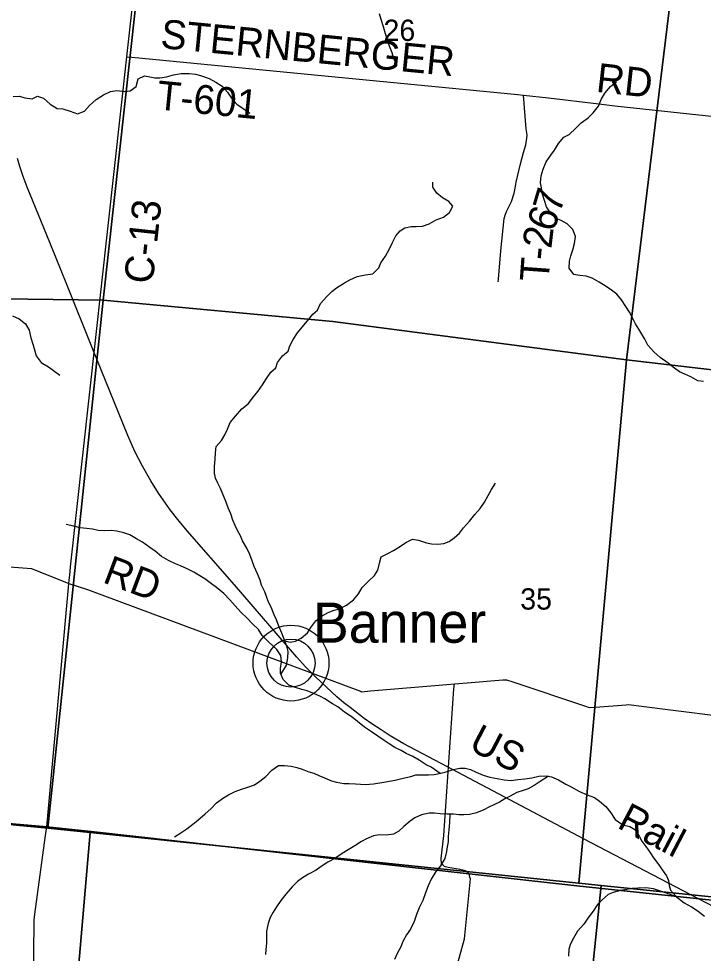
# Model space of a CAD drawing. Extents: x 1715311 to 2083412, y 146837 to 553079.
# Drawn here: x 1938656 to 1945751, y 339371 to 349055 of the extents above; entities that cross this region are included whole.
import ezdxf

# ---------------------------------------------------------------- set-up
doc = ezdxf.new("R2010")
doc.units = 0
for name, color, linetype in [('GM_X_County_Road', 7, 'Continuous'), ('GM_X_County_Road_Text', 7, 'Continuous'), ('GM_X_Major_River', 7, 'Continuous'), ('GM_X_Minor_River', 7, 'Continuous'), ('GM_X_Rail_Line', 7, 'Continuous'), ('GM_X_Rail_Line_Text', 7, 'Continuous'), ('GM_X_Section', 7, 'Continuous'), ('GM_X_Section_Text', 7, 'Continuous'), ('GM_X_Township', 7, 'Continuous'), ('GM_X_Township_Road', 7, 'Continuous'), ('GM_X_Township_Road_Text', 7, 'Continuous'), ('GM_X_Unincorporated', 7, 'Continuous'), ('GM_X_Unincorporated_Location', 7, 'Continuous'), ('GM_X_Unincorporated_Text', 7, 'Continuous')]:
    doc.layers.add(name, color=color, linetype=linetype)

msp = doc.modelspace()

# ---------------------------------------------------------------- linework, layer by layer
at = {"layer": 'GM_X_County_Road'}
for points in [[(1938935.2, 340590.1), (1938947.9, 340681.2), (1939172.8, 343162.1), (1939176.8, 343201), (1939183.7, 343268), (1939185, 343285.8), (1939194.7, 343373.7), (1939777.7, 348661.1), (1939894.4, 349718.8), (1939895.9, 349732.8), (1939820.2, 349785.7), (1939515.1, 349999.1), (1939497.4, 350011.3), (1939503.1, 350096.1), (1939538.8, 350627.1), (1939541.5, 350666.8), (1939516.4, 350728.3), (1939415.8, 350974.7), (1939407.4, 350995.5), (1939345.3, 351051.9), (1939188, 351195.2), (1939148.3, 351231.3)], [(1931545.1, 344105.6), (1934080.4, 345204.9), (1934175.4, 345216.4), (1934810.6, 345293.7), (1935110.9, 344920.9), (1935323.1, 343756.7), (1935469.2, 343608.4), (1938788.6, 343357.9), (1939176.8, 343201)], [(1939176.8, 343201), (1939370, 343141), (1942197.7, 342086.2), (1942210, 342081.6), (1942302.3, 342089.4), (1943093.7, 342157.2), (1943171, 342163.7), (1943304.8, 342174.2), (1943674.3, 342203.1), (1943709.5, 342205.8), (1943776.4, 342183.3), (1944529.4, 341930.5), (1944568.4, 341917.3), (1944632.8, 341922), (1944949.7, 341945.2), (1944978.8, 341947.3), (1945054.9, 341937.7), (1946315.5, 341777.9)], [(1943060.7, 340276.9), (1943038.5, 340300.6), (1943032.8, 340353.3), (1943061, 340592.3), (1943165.7, 342109.8), (1943171, 342163.7)], [(1938808.1, 339138.3), (1938815.9, 339670.2), (1938816.6, 339717.3), (1938822.6, 339776.1), (1938935.2, 340590.1)], [(1943332.5, 340160.3), (1943322.9, 340193.4), (1943291.1, 340224.1), (1943209.7, 340244.2), (1943108.1, 340259.2), (1943066.7, 340270.5), (1943060.7, 340276.9)], [(1943194.4, 339218.7), (1943275.6, 339519.6), (1943337.7, 340142.5), (1943332.5, 340160.3)]]:
    msp.add_lwpolyline(points, dxfattribs=at)
at = {"layer": 'GM_X_Major_River'}
msp.add_lwpolyline([(1942390.9, 349109.3), (1942408.3, 349051.1), (1942433.6, 348972.8), (1942454.9, 348902.6), (1942476.3, 348834.4), (1942495.7, 348774.1), (1942523, 348705.8), (1942540.4, 348645.6), (1942571.8, 348579.3)], dxfattribs=at)
at = {"layer": 'GM_X_Minor_River'}
for points in [[(1938598.9, 348247.8), (1938664.8, 348251.5), (1938720.6, 348233.2), (1938796.4, 348224.8), (1938852.4, 348252.6), (1938914.1, 348230.3), (1938983.7, 348168), (1939055.3, 348125.6), (1939115.2, 348121.3), (1939190.9, 348095), (1939264.6, 348068.6), (1939336.6, 348096.3), (1939388.7, 348154.1), (1939458.8, 348215.8), (1939536.9, 348265.5), (1939606.9, 348301.2), (1939672.8, 348309), (1939756.5, 348300.6), (1939810.5, 348306.3), (1939872.5, 348352.1), (1939894.8, 348430), (1939958.8, 348461.8), (1940014.6, 348453.5), (1940066.5, 348441.3), (1940120.3, 348441), (1940186.3, 348452.7), (1940262.2, 348474.4), (1940340.1, 348486.1), (1940423.9, 348485.7), (1940489.7, 348479.4), (1940541.5, 348467.1), (1940629.2, 348434.7), (1940698.9, 348398.4), (1940764.5, 348356.1), (1940820.1, 348291.8), (1940861.8, 348229.5), (1940915.4, 348167.3), (1940983.1, 348124.9), (1941050.7, 348076.6)], [(1945752, 345296), (1945694.1, 345302.2), (1945622.5, 345344.6), (1945560.7, 345370.9), (1945505, 345395.1), (1945451.3, 345433.4), (1945385.6, 345485.7), (1945304.1, 345544.1), (1945238.5, 345602.4), (1945176.9, 345670.7), (1945143.3, 345732.9), (1945113.6, 345785.1), (1945081.9, 345839.2), (1945048.2, 345893.4), (1945014.6, 345963.6), (1944984.8, 346013.8), (1944949.2, 346072), (1944903.6, 346140.2), (1944854, 346200.5), (1944800.3, 346240.7), (1944742.6, 346279), (1944672.9, 346325.3), (1944597.3, 346367.7), (1944535.5, 346388), (1944469.7, 346392.3), (1944407.8, 346402.6), (1944360.2, 346470.8), (1944362.6, 346542.8), (1944376.8, 346598.8), (1944397, 346660.8), (1944417.2, 346726.7), (1944425.5, 346796.7), (1944397.9, 346870.9), (1944338.3, 346929.2), (1944278.6, 346963.5), (1944224.8, 346983.7), (1944159.2, 347052), (1944125.6, 347106.2), (1944099.9, 347180.4), (1944080.3, 347248.5), (1944072.5, 347302.6), (1944064.8, 347352.6), (1944069.1, 347424.7), (1944091.3, 347496.6), (1944123.6, 347572.5), (1944171.8, 347640.3), (1944207.9, 347692.2), (1944250.1, 347762.1), (1944306.3, 347825.9), (1944360.3, 347855.6), (1944428.4, 347919.4), (1944486.5, 347975.2), (1944558.6, 348026.9), (1944610.7, 348080.7), (1944662.9, 348148.5), (1944693.1, 348216.4), (1944731.3, 348284.3), (1944787.5, 348352.1), (1944849.6, 348403.8)], [(1941373.9, 342259.9), (1941430.9, 342355.8), (1941445.2, 342433.8), (1941447.5, 342497.8), (1941433.7, 342551.9), (1941382.4, 342688.2), (1941352.8, 342760.3), (1941327.2, 342826.5), (1941303.4, 342878.6), (1941271.9, 342956.8), (1941246.1, 343008.9), (1941226.4, 343059), (1941206.7, 343115.2), (1941173.1, 343185.3), (1941157.3, 343235.5), (1941129.7, 343303.6), (1941098.1, 343377.8), (1941076.4, 343435.9), (1941052.7, 343502), (1941019.1, 343568.2), (1940975.5, 343644.5), (1940953.8, 343696.6), (1940924.1, 343752.7), (1940900.4, 343804.9), (1940874.7, 343857), (1940853, 343923.1), (1940827.3, 343987.3), (1940799.7, 344061.4), (1940772.1, 344127.6), (1940746.4, 344185.7), (1940718.7, 344241.9), (1940695, 344294), (1940685.2, 344346.1), (1940685.5, 344416.1), (1940693.9, 344492.1), (1940696.1, 344556.1), (1940702.4, 344622.1), (1940756.5, 344683.9), (1940792.7, 344741.8), (1940818.9, 344801.7), (1940849.2, 344869.6), (1940901.3, 344937.4), (1940969.5, 345011.1), (1941035.6, 345062.9), (1941089.8, 345136.7), (1941135.9, 345190.5), (1941184.1, 345260.3), (1941224.3, 345328.2), (1941268.5, 345392), (1941320.6, 345437.8), (1941338.8, 345491.8), (1941389, 345561.6), (1941449, 345611.3), (1941465.2, 345663.3), (1941499.4, 345729.2), (1941545.7, 345801), (1941593.8, 345856.8), (1941650, 345924.6), (1941704.1, 345992.4), (1941754.2, 346036.2), (1941782.5, 346104.1), (1941850.6, 346177.8), (1941900.7, 346229.6), (1941950.8, 346267.5), (1942030.8, 346319.1), (1942088.8, 346348.9), (1942162.8, 346382.6), (1942250.7, 346402.2), (1942324.6, 346411.8), (1942386.7, 346471.6), (1942408.9, 346523.5), (1942457.1, 346595.4), (1942497.3, 346669.2), (1942529.5, 346735.1), (1942565.7, 346805), (1942607.9, 346856.8), (1942657.9, 346886.6), (1942723.8, 346900.4), (1942775.7, 346900.1), (1942841.6, 346903.8), (1942911.5, 346927.5), (1942981.5, 346969.2), (1943057.5, 346998.9), (1943119.6, 347046.7), (1943153.8, 347110.6), (1943112.1, 347160.8), (1943048.4, 347197.1), (1942988.7, 347247.4), (1942949.1, 347309.6), (1942949.3, 347361.6)], [(1938593, 345976.3), (1938660.7, 345944), (1938726.4, 345893.7), (1938766, 345827.5), (1938783.6, 345749.4), (1938805.2, 345673.2), (1938819, 345623.1), (1938838.7, 345561), (1938890.2, 345492.7), (1938963.9, 345446.4), (1939015.6, 345408.1), (1939083.2, 345359.8)], [(1941412.7, 342607.7), (1941467.8, 342595.8), (1941523.8, 342605.5), (1941583.8, 342637.3), (1941647.9, 342693), (1941684, 342744.9), (1941736.2, 342816.7), (1941800.3, 342866.4), (1941862.3, 342902.1), (1941924.3, 342927.9), (1941980.2, 342941.6), (1942052.2, 342977.3), (1942126.3, 343033), (1942176.4, 343096.8), (1942216.6, 343160.7), (1942276.8, 343224.4), (1942344.9, 343286.1), (1942377.1, 343340), (1942395.3, 343412), (1942413.6, 343479.9), (1942489.6, 343517.6), (1942541.6, 343545.4), (1942603.6, 343583.1), (1942669.6, 343626.8), (1942737.6, 343660.6), (1942799.5, 343652.3), (1942883.1, 343623.9), (1942935, 343613.6), (1943000.8, 343609.4), (1943062.7, 343617.1), (1943118.7, 343638.8), (1943168.7, 343674.6), (1943222.8, 343724.4), (1943267, 343780.2), (1943327.1, 343848), (1943383.3, 343917.8), (1943437.5, 343979.6), (1943481.6, 344045.4), (1943519.9, 344115.3), (1943554.1, 344175.2), (1943596.3, 344243)], [(1943024.6, 341234.9), (1942930.9, 341298.6), (1942877.1, 341324.9), (1942807.5, 341373.2), (1942739.8, 341409.5), (1942672.1, 341441.8), (1942618.4, 341472.1), (1942552.6, 341504.4), (1942496.9, 341540.7), (1942445.2, 341576.9), (1942377.6, 341621.2), (1942313.9, 341665.6), (1942238.3, 341713.9), (1942166.7, 341772.3), (1942113, 341816.5), (1942033.4, 341868.9), (1941961.8, 341923.2), (1941908.1, 341955.5), (1941828.5, 342005.9), (1941776.7, 342034.1), (1941722.9, 342060.4), (1941645.2, 342088.8), (1941591.4, 342105), (1941523.7, 342123.3), (1941455.9, 342147.6), (1941396.3, 342207.9), (1941368.7, 342272.1), (1941368.9, 342322.1), (1941379.1, 342390.1), (1941371.4, 342456.1), (1941331.8, 342520.3), (1941248.3, 342594.8), (1941180.8, 342665.1), (1941141.1, 342727.3), (1941077.5, 342783.6), (1941023.9, 342841.9), (1940958.3, 342906.2), (1940900.7, 342970.5), (1940845.2, 343034.8), (1940783.6, 343099.1), (1940706, 343161.4), (1940654.3, 343197.7), (1940586.7, 343250), (1940532.9, 343282.3), (1940471.2, 343318.6), (1940401.5, 343352.9), (1940333.8, 343385.2), (1940280, 343407.5), (1940208.4, 343441.8), (1940136.7, 343482.1), (1940069.1, 343536.5), (1940015.4, 343576.7), (1939939.8, 343629.1), (1939878.1, 343665.4), (1939806.4, 343705.7), (1939746.6, 343726), (1939674.9, 343746.3), (1939615, 343750.6), (1939545.2, 343748.9), (1939479.3, 343753.2), (1939419.5, 343765.5), (1939361.7, 343771.8), (1939291.9, 343780.1), (1939228.1, 343796.4), (1939148.3, 343812.7)], [(1940271.7, 340576.3), (1940337.8, 340620), (1940397.8, 340661.8), (1940461.9, 340709.5), (1940511.9, 340751.3), (1940588, 340815), (1940648.1, 340868.7), (1940706.3, 340930.5), (1940780.3, 340980.2), (1940830.4, 341012), (1940898.4, 341047.7), (1940966.3, 341071.4), (1941032.3, 341091.1), (1941098.2, 341116.8), (1941154.3, 341154.6), (1941218.3, 341202.3), (1941278.5, 341270), (1941348.5, 341315.8), (1941412.4, 341317.5), (1941478.2, 341311.2), (1941538, 341296.9), (1941593.8, 341278.6), (1941661.5, 341252.3), (1941713.4, 341236.1), (1941765.2, 341213.8), (1941824.9, 341187.5), (1941896.6, 341159.2), (1941950.4, 341143), (1942024.2, 341130.6), (1942082.1, 341130.4), (1942145.9, 341128.1), (1942197.8, 341121.8), (1942251.7, 341121.6), (1942333.5, 341125.2), (1942441.3, 341144.8), (1942497.3, 341154.5), (1942557.2, 341166.2), (1942639.1, 341185.9), (1942719, 341203.5), (1942772.9, 341219.3), (1942902.6, 341218.7), (1942960.5, 341224.5), (1943032.4, 341236.1), (1943084.4, 341251.9), (1943158.3, 341273.6), (1943228.2, 341289.3), (1943284.1, 341289), (1943337.9, 341274.8), (1943395.6, 341246.5), (1943469.3, 341218.2), (1943539.1, 341195.8), (1943614.9, 341181.5), (1943688.6, 341167.2), (1943760.4, 341160.8), (1943830.3, 341170.5), (1943900.2, 341178.2), (1943974.1, 341189.9), (1944046, 341205.6), (1944115.9, 341211.3), (1944177.7, 341199), (1944249.4, 341168.6), (1944325, 341122.3), (1944382.7, 341094), (1944468.4, 341047.6), (1944546, 341013.2), (1944621.7, 340984.9), (1944673.5, 340948.6), (1944739.1, 340890.3), (1944792.7, 340826), (1944838.2, 340755.8), (1944917.8, 340703.4), (1944987.6, 340685.1), (1945039.3, 340652.8), (1945084.9, 340584.6), (1945114.7, 340532.5), (1945156.3, 340476.2), (1945203.9, 340410), (1945233.6, 340359.8), (1945289.2, 340287.6), (1945324.9, 340237.4), (1945370.5, 340175.1), (1945388.3, 340125), (1945398, 340075), (1945411.8, 340024.9), (1945471.3, 339954.6), (1945552.9, 339892.2), (1945628.5, 339853.8), (1945698.2, 339807.5), (1945763.8, 339757.2)], [(1944146.9, 341205.1), (1944059.7, 341149.5), (1943997.7, 341109.7), (1943935.7, 341074), (1943883.7, 341058.2), (1943817.8, 341036.5), (1943747.8, 340998.8), (1943693.8, 340971), (1943639.7, 340937.3), (1943585.7, 340911.5), (1943529.8, 340885.7), (1943475.7, 340856), (1943401.8, 340826.3), (1943327.9, 340810.6), (1943268, 340804.9), (1943216.1, 340807.1), (1943162.3, 340813.4), (1943092.4, 340813.7), (1943022.6, 340816), (1942966.8, 340824.2), (1942908.9, 340824.5), (1942831, 340806.8), (1942763, 340775.1), (1942713, 340741.4), (1942648.9, 340683.6), (1942594.8, 340635.8), (1942538.8, 340604.1), (1942464.9, 340594.4), (1942395.1, 340596.7), (1942333.1, 340587), (1942259.2, 340555.3), (1942209.2, 340529.5), (1942141.1, 340483.8), (1942071.1, 340444.1), (1942007.1, 340404.4), (1941933, 340352.7), (1941861, 340315), (1941791, 340269.3), (1941738.9, 340233.5), (1941660.9, 340191.9), (1941596.9, 340154.1), (1941544.9, 340116.3), (1941488.7, 340060.6), (1941424.6, 339984.8), (1941374.4, 339919), (1941328.2, 339851.2), (1941294, 339797.3), (1941261.9, 339743.5), (1941241.6, 339679.5), (1941223.3, 339599.6), (1941222.8, 339477.5), (1941216.5, 339411.5), (1941212.3, 339357.5)], [(1943124.4, 340813.5), (1943122, 340725.5), (1943113.7, 340649.5), (1943107.4, 340581.5), (1943105.2, 340527.5), (1943097, 340475.5), (1943090.7, 340425.5), (1943072.5, 340351.5), (1943028.2, 340275.7), (1942978.1, 340217.9), (1942931.9, 340140.1), (1942899.6, 340070.2), (1942873.4, 339996.3), (1942843.1, 339916.4), (1942806.8, 339842.5), (1942778.6, 339772.6), (1942754.3, 339698.7), (1942718.1, 339620.8), (1942675.9, 339561), (1942637.7, 339493.1), (1942615.5, 339439.2), (1942583.3, 339375.3), (1942551.1, 339307.4)], [(1945471.3, 339954.6), (1945369.7, 339995), (1945308, 340015.3), (1945234.2, 340039.7), (1945156.5, 340050), (1945072.6, 340046.4), (1945010.7, 340040.7), (1944958.8, 340032.9), (1944890.9, 340021.2), (1944817, 339999.5), (1944765, 339979.8), (1944702.9, 339926), (1944652.8, 339876.2), (1944608.6, 339808.4), (1944554.4, 339734.6), (1944512.3, 339672.7), (1944446.1, 339599), (1944405.9, 339529.2), (1944373.7, 339467.3), (1944357.5, 339413.3), (1944353.2, 339341.3)]]:
    msp.add_lwpolyline(points, dxfattribs=at)
at = {"layer": 'GM_X_Rail_Line'}
msp.add_lwpolyline([(1946019.2, 339769.3), (1944516, 340553.9), (1943092.4, 341306.1), (1942646.7, 341541.6), (1942506.5, 341625.6), (1942412.1, 341684.9), (1942315.5, 341749.6), (1942236.4, 341804.4), (1942089.9, 341916.3), (1942027, 341965.3), (1941952.4, 342028.2), (1941845, 342127.1), (1941732.7, 342234), (1941627.5, 342340.5), (1941538.5, 342439.4), (1940891.9, 343187.1), (1940403, 343748.4), (1940305, 343864.3), (1940227.7, 343966.8), (1940106.4, 344137.5), (1940025.5, 344267), (1939940.2, 344417.9), (1939861.1, 344570.7), (1939787.4, 344737), (1939421.6, 345637.5), (1939153.8, 346299), (1938977.6, 346734.9), (1938744.8, 347307.4), (1938703.5, 347419.7), (1938668.5, 347522.1), (1938642.4, 347604.8)], dxfattribs=at)
at = {"layer": 'GM_X_Section'}
for points in [[(1940088.2, 351180.6), (1939532.8, 346138.3), (1934334.2, 346205.8), (1935113.9, 351673.9)], [(1945586.7, 350703), (1944953.2, 345520.7), (1941911, 345916.7), (1939532.8, 346138.3), (1940088.2, 351180.6)], [(1950879.1, 350205.5), (1950647.4, 347751.3), (1950377.5, 344887), (1944953.2, 345520.7), (1945586.7, 350703)], [(1934334.2, 346205.8), (1939532.8, 346138.3), (1938957.1, 340668), (1934014.7, 341139.4), (1933604.7, 341179.7)], [(1939532.8, 346138.3), (1941911, 345916.7), (1944953.2, 345520.7), (1944461.5, 340096.3), (1939397.1, 340621.7), (1938957.1, 340668)], [(1944953.2, 345520.7), (1950377.5, 344887), (1950143.9, 342436.8), (1949863.9, 339540.6), (1944691.5, 340074.1), (1944461.5, 340096.3)], [(1938957.1, 340668), (1939397.1, 340621.7), (1938923.4, 335133.3), (1933565, 335605), (1934014.7, 341139.4)], [(1939397.1, 340621.7), (1944461.5, 340096.3), (1944691.5, 340074.1), (1944133.8, 334673.8), (1938923.4, 335133.3)], [(1949863.9, 339540.6), (1949642.3, 337194.4), (1949380.3, 334200.2), (1944133.8, 334673.8), (1944691.5, 340074.1)]]:
    msp.add_lwpolyline(points, close=True, dxfattribs=at)
at = {"layer": 'GM_X_Township'}
for points in [[(1952285.1, 364266.3), (1952228.9, 363880.2), (1952101.7, 362654.2), (1951671.7, 358398.8), (1951408.1, 355623.4), (1951377.5, 355526.7), (1951154.1, 353065.4), (1950967.1, 351172.6), (1950868.7, 350176.4), (1950619.5, 347730.7), (1950491.7, 346400.3), (1950342.6, 344848.7), (1950219.2, 343469.8), (1950123.7, 342403.1), (1949931.4, 340559.6), (1949822.6, 339497.5), (1949613.9, 339519.7), (1944440.4, 340068.4), (1943322.9, 340193.4), (1939406.5, 340631.2), (1938947.9, 340681.2), (1938231.9, 340743.6)], [(1917500.7, 336917.9), (1917737.8, 339603.6), (1917862.7, 341233.1), (1917980.7, 342685.3), (1919669, 342538.5), (1924036.1, 342100.7), (1925166.1, 341982.1), (1928217.1, 341681.9), (1928821, 341629), (1932943.7, 341230.5), (1933753.2, 341150.1), (1938231.9, 340743.6), (1938947.9, 340681.2), (1939406.5, 340631.2), (1943322.9, 340193.4), (1944440.4, 340068.4), (1949613.9, 339519.7), (1949822.6, 339497.5), (1949762.5, 338856.4)]]:
    msp.add_lwpolyline(points, dxfattribs=at)
at = {"layer": 'GM_X_Township_Road'}
for points in [[(1939777.7, 348661.1), (1939830.2, 348655.6), (1943828, 348269.4)], [(1943626.5, 346327.4), (1943629.1, 346356.7), (1943651, 346648.2), (1943686.9, 346985.7), (1943699.6, 347028.2), (1943715, 347062.6), (1943762.9, 347161.2), (1943791, 347247.1), (1943800.9, 347297.8), (1943811.8, 347359.3), (1943824.4, 347419), (1943852.5, 347537.6), (1943888.7, 347669.6), (1943912.2, 347748.4), (1943918.5, 347793.6), (1943924, 347843.3), (1943923, 347872.3), (1943916.7, 347912.1), (1943885.9, 348263.8)], [(1943828, 348269.4), (1943885.9, 348263.8), (1944147.4, 348234.2), (1944668, 348172.8)], [(1944668, 348172.8), (1944835, 348153.1), (1946544.4, 347967.9), (1948564.4, 347774.6), (1948716.6, 347769.6)]]:
    msp.add_lwpolyline(points, dxfattribs=at)
at = {"layer": 'GM_X_Unincorporated'}
for radius in [392.8, 249]:
    msp.add_circle((1941478.1, 342377.6), radius, dxfattribs=at)
at = {"layer": 'GM_X_Unincorporated_Location'}
msp.add_line((1941478.1, 342377.6), (1941478.1, 342377.6), dxfattribs=at)

# ---------------------------------------------------------------- texts
at = {"layer": 'GM_X_County_Road_Text'}
for s, rotation, p in [('C-13', 83.81086, (1940044.4, 346298.9)), ('RD', 339.38816, (1939515, 343218.3))]:
    msp.add_text(s, height=300, rotation=rotation, dxfattribs=at).set_placement(p)
at = {"layer": 'GM_X_Rail_Line_Text'}
for s, rotation, p in [('US', 332.35461, (1943305.7, 341490.9)), ('Rail', 332.32854, (1944845.9, 340677))]:
    msp.add_text(s, height=299, rotation=rotation, dxfattribs=at).set_placement(p)
at = {"layer": 'GM_X_Section_Text'}
for s, p in [('26', (1942436.8, 348823.8)), ('35', (1943853.6, 342932.2))]:
    msp.add_text(s, height=221, rotation=0.00001, dxfattribs=at).set_placement(p)
at = {"layer": 'GM_X_Township_Road_Text'}
for s, rotation, p in [('STERNBERGER', 354.48185, (1940118.4, 348751.8)), ('RD', 353.60721, (1944631.7, 348298.1)), ('T-601', 354.3731, (1940078, 348116.1)), ('7', 73.48338, (1944265.2, 347026.1)), ('6', 69.30325, (1944192.3, 346830.6)), ('2', 83.30809, (1944175.4, 346665.9)), ('-', 84.37872, (1944163.5, 346544.7)), ('T', 85.87376, (1944147.5, 346323))]:
    msp.add_text(s, height=300, rotation=rotation, dxfattribs=at).set_placement(p)
at = {"layer": 'GM_X_Unincorporated_Text'}
msp.add_text('Banner', height=417, rotation=0.00001, dxfattribs=at).set_placement((1941704.2, 342588.5))

doc.saveas('drawing.dxf')
